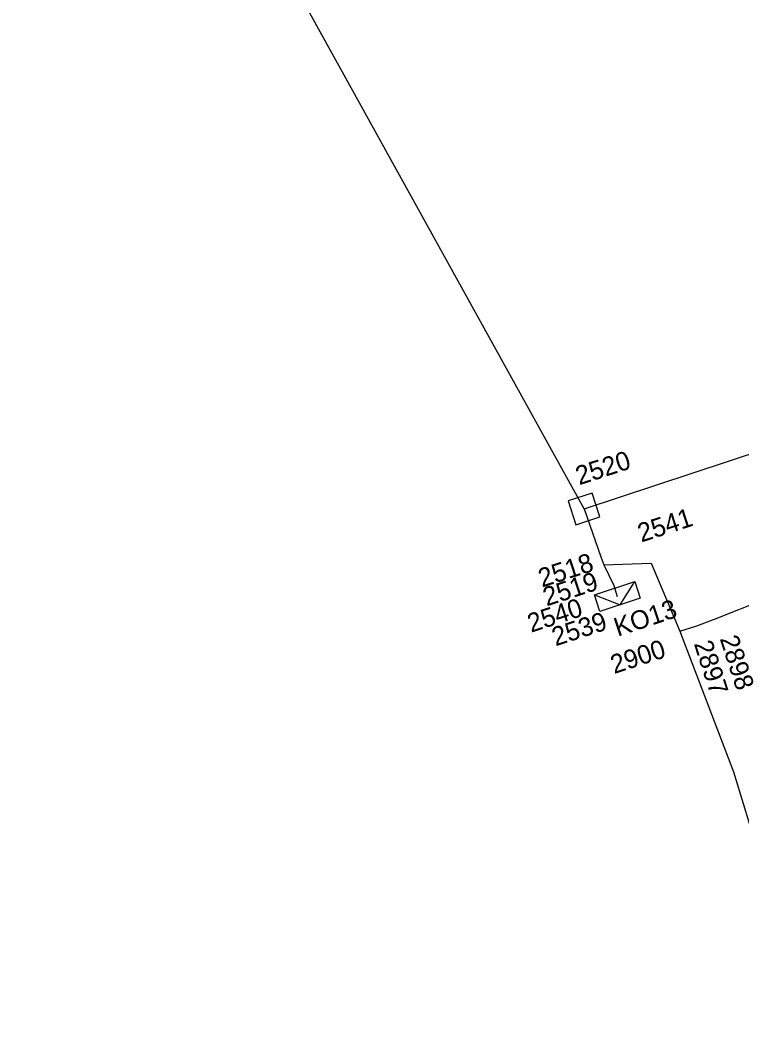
# Model space of a CAD drawing. Extents: x -535557 to -534097, y -1142175 to -1136716.
# Drawn here: x -534974.06 to -534945.19, y -1138989.06 to -1138949.07 of the extents above; entities that cross this region are included whole.
import ezdxf

# ---------------------------------------------------------------- set-up
doc = ezdxf.new("R2010")
doc.units = 0
doc.layers.add('Default', color=7, linetype='Continuous')
doc.layers.add('SS_SZDC', color=7, linetype='Continuous')

# ---------------------------------------------------------------- blocks, each defined once
blk = doc.blocks.new('POINT_DISPLAY')
at = {"layer": 'Default'}
blk.add_line((0, 0), (0, 0), dxfattribs=at)

msp = doc.modelspace()

# ---------------------------------------------------------------- linework, layer by layer
at = {"layer": 'SS_SZDC'}
for p, q in [((-534951.51, -1138968.6), (-534974.06, -1138927.84)), ((-534951.51, -1138968.6), (-534926.84, -1138960.43)), ((-534951.188, -1138967.969), (-534952.14, -1138968.278)), ((-534950.879, -1138968.921), (-534951.188, -1138967.969)), ((-534952.14, -1138968.278), (-534951.831, -1138969.23)), ((-534951.51, -1138968.6), (-534950.84, -1138970.52)), ((-534951.831, -1138969.23), (-534950.879, -1138968.921)), ((-534950.84, -1138970.52), (-534950.72, -1138970.84)), ((-534950.72, -1138970.84), (-534948.819, -1138970.77)), ((-534948.819, -1138970.77), (-534947.68, -1138973.489)), ((-534950.72, -1138970.84), (-534950.319, -1138971.659)), ((-534951.096, -1138972.029), (-534949.479, -1138971.504)), ((-534950.071, -1138972.432), (-534949.479, -1138971.504)), ((-534949.479, -1138971.504), (-534949.263, -1138972.17)), ((-534950.319, -1138971.659), (-534950.18, -1138972.1)), ((-534946.289, -1138973.01), (-534943.46, -1138971.879)), ((-534950.88, -1138972.695), (-534951.096, -1138972.029)), ((-534951.096, -1138972.029), (-534950.071, -1138972.432)), ((-534949.263, -1138972.17), (-534950.88, -1138972.695)), ((-534947, -1138973.27), (-534946.289, -1138973.01)), ((-534947.68, -1138973.489), (-534947, -1138973.27)), ((-534947.68, -1138973.489), (-534945.529, -1138979.11)), ((-534945.529, -1138979.11), (-534942.51, -1138989.059))]:
    msp.add_line(p, q, dxfattribs=at)

# ---------------------------------------------------------------- block references
for p in [(-534951.51, -1138968.6), (-534950.84, -1138970.52), (-534948.819, -1138970.77), (-534950.72, -1138970.84), (-534950.319, -1138971.659), (-534950.18, -1138972.1), (-534946.289, -1138973.01), (-534947.68, -1138973.489), (-534947, -1138973.27), (-534945.529, -1138979.11)]:
    msp.add_blockref('POINT_DISPLAY', p, dxfattribs=at)

# ---------------------------------------------------------------- texts
for s, rotation, p in [('2520', 18, (-534951.702, -1138967.657)), ('2541', 18, (-534949.22, -1138969.943)), ('2518', 18, (-534953.19, -1138971.745)), ('2519', 18, (-534953.005, -1138972.496)), ('2540', 18, (-534953.627, -1138973.548)), ('KO13', 18.3757, (-534950.163, -1138973.711)), ('2539', 18, (-534952.651, -1138974.092)), ('2900', 18, (-534950.306, -1138975.198)), ('2897', 288, (-534947.123, -1138973.985)), ('2898', 288, (-534946.087, -1138973.783))]:
    msp.add_text(s, height=0.75, rotation=rotation, dxfattribs=at).set_placement(p)

doc.saveas('drawing.dxf')
